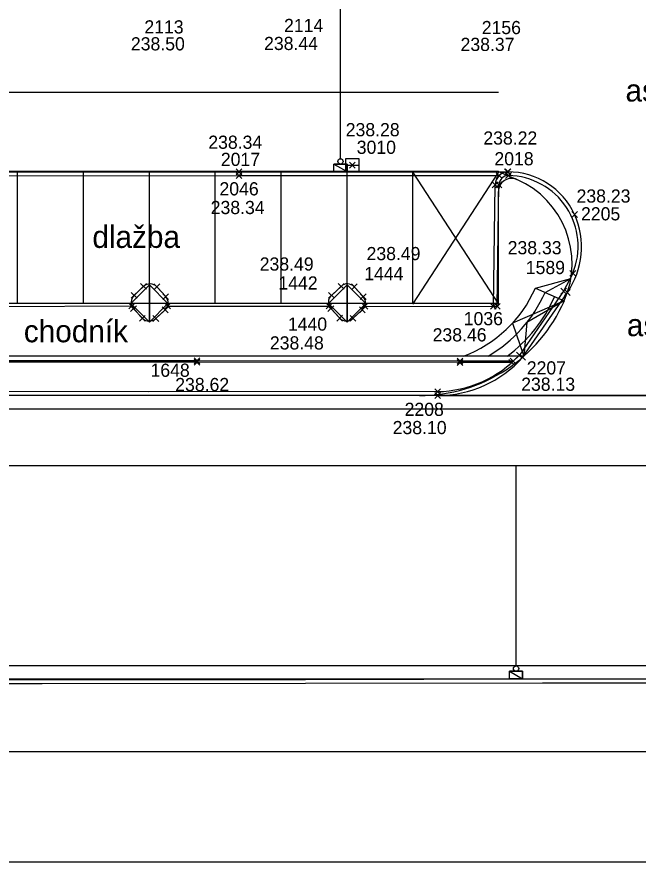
# Model space of a CAD drawing. Extents: x -264165 to -263733, y -1242319 to -1242245.
# Drawn here: x -263947.85 to -263924.28, y -1242319.19 to -1242287.11 of the extents above; entities that cross this region are included whole.
import ezdxf

# ---------------------------------------------------------------- set-up
doc = ezdxf.new("R2010")
doc.units = 0
for name, color, linetype in [('KFA_BOD_CISLO', 7, 'Continuous'), ('KFA_BOD_SYMBOL', 7, 'Continuous'), ('KFA_BOD_VYSKA', 7, 'Continuous'), ('KFA_SO_20-2_OBRUBNIKY_DOLNA_HRANA', 7, 'Continuous'), ('KFA_SO_20-2_OBRUBNIKY_HORNA_HRANA', 7, 'Continuous'), ('KFA_UV_BOD_CISLO', 7, 'Continuous'), ('KFA_UV_BOD_SYMBOL', 7, 'Continuous'), ('KFA_UV_BOD_VYSKA', 7, 'Continuous'), ('POPIS', 7, 'Continuous'), ('PROJEKT_OBRUBNIKY_KOMUNIKACIE', 7, 'Continuous'), ('PROJEKT_TDZ_VODOROVNE', 7, 'Continuous'), ('RAM_NA_TLAC_1-250', 7, 'Continuous'), ('ROZHRANIE_SO_20-1_a_20-2', 7, 'Continuous'), ('SITUACIA_DSP_2D', 7, 'Continuous'), ('SO_20-1_OBRUBNIKY_DOLNA_HRANA', 7, 'Continuous'), ('SO_20-1_OBRUBNIKY_HORNA_HRANA', 7, 'Continuous'), ('ULICNA_VPUST_POKLOP', 7, 'Continuous')]:
    doc.layers.add(name, color=color, linetype=linetype)

msp = doc.modelspace()

# ---------------------------------------------------------------- linework, layer by layer
at = {"layer": 'KFA_BOD_SYMBOL'}
for p, q in [((-263939.535, -1242293.244), (-263939.313, -1242293.022)), ((-263939.313, -1242293.244), (-263939.535, -1242293.022)), ((-263939.534, -1242293.1), (-263939.312, -1242292.88)), ((-263939.312, -1242293.1), (-263939.534, -1242292.88)), ((-263929.666, -1242293.244), (-263929.444, -1242293.022)), ((-263929.444, -1242293.244), (-263929.666, -1242293.022)), ((-263929.348, -1242293.1), (-263929.127, -1242292.879)), ((-263929.127, -1242293.1), (-263929.348, -1242292.879)), ((-263929.33, -1242293.099), (-263929.109, -1242292.877)), ((-263929.109, -1242293.099), (-263929.33, -1242292.877)), ((-263929.311, -1242293.24), (-263929.09, -1242293.019)), ((-263929.09, -1242293.24), (-263929.311, -1242293.019)), ((-263929.818, -1242293.593), (-263929.596, -1242293.372)), ((-263929.596, -1242293.593), (-263929.818, -1242293.372)), ((-263929.676, -1242293.592), (-263929.454, -1242293.37)), ((-263929.454, -1242293.592), (-263929.676, -1242293.37)), ((-263926.801, -1242294.718), (-263926.579, -1242294.497)), ((-263926.579, -1242294.718), (-263926.801, -1242294.497)), ((-263926.871, -1242296.953), (-263926.649, -1242296.731)), ((-263926.649, -1242296.953), (-263926.871, -1242296.731)), ((-263943.155, -1242297.448), (-263942.934, -1242297.227)), ((-263942.934, -1242297.448), (-263943.155, -1242297.227)), ((-263935.66, -1242297.448), (-263935.439, -1242297.227)), ((-263935.439, -1242297.448), (-263935.66, -1242297.227)), ((-263942.652, -1242297.463), (-263942.431, -1242297.242)), ((-263942.431, -1242297.463), (-263942.652, -1242297.242)), ((-263935.16, -1242297.464), (-263934.939, -1242297.242)), ((-263934.939, -1242297.464), (-263935.16, -1242297.242)), ((-263927.218, -1242297.626), (-263926.997, -1242297.404)), ((-263926.997, -1242297.626), (-263927.218, -1242297.404)), ((-263927.078, -1242297.681), (-263926.856, -1242297.46)), ((-263926.856, -1242297.681), (-263927.078, -1242297.46)), ((-263943.513, -1242297.785), (-263943.291, -1242297.565)), ((-263943.291, -1242297.785), (-263943.513, -1242297.565)), ((-263942.316, -1242297.836), (-263942.095, -1242297.616)), ((-263942.095, -1242297.836), (-263942.316, -1242297.616)), ((-263936.025, -1242297.789), (-263935.804, -1242297.568)), ((-263935.804, -1242297.789), (-263936.025, -1242297.568)), ((-263934.824, -1242297.835), (-263934.603, -1242297.613)), ((-263934.603, -1242297.835), (-263934.824, -1242297.613)), ((-263943.6, -1242298.19), (-263943.378, -1242297.968)), ((-263943.378, -1242298.19), (-263943.6, -1242297.968)), ((-263943.534, -1242298.293), (-263943.312, -1242298.073)), ((-263943.312, -1242298.293), (-263943.534, -1242298.073)), ((-263942.334, -1242298.336), (-263942.112, -1242298.116)), ((-263942.112, -1242298.336), (-263942.334, -1242298.116)), ((-263942.242, -1242298.194), (-263942.02, -1242297.974)), ((-263942.02, -1242298.194), (-263942.242, -1242297.974)), ((-263936.115, -1242298.194), (-263935.894, -1242297.972)), ((-263935.894, -1242298.194), (-263936.115, -1242297.972)), ((-263936.052, -1242298.289), (-263935.831, -1242298.069)), ((-263935.831, -1242298.289), (-263936.052, -1242298.069)), ((-263934.856, -1242298.335), (-263934.635, -1242298.113)), ((-263934.635, -1242298.335), (-263934.856, -1242298.113)), ((-263934.759, -1242298.198), (-263934.538, -1242297.978)), ((-263934.538, -1242298.198), (-263934.759, -1242297.978)), ((-263929.883, -1242298.204), (-263929.661, -1242297.984)), ((-263929.661, -1242298.204), (-263929.883, -1242297.984)), ((-263929.736, -1242298.204), (-263929.514, -1242297.984)), ((-263929.514, -1242298.204), (-263929.736, -1242297.984)), ((-263943.198, -1242298.659), (-263942.977, -1242298.438)), ((-263942.977, -1242298.659), (-263943.198, -1242298.438)), ((-263942.692, -1242298.667), (-263942.47, -1242298.447)), ((-263942.47, -1242298.667), (-263942.692, -1242298.447)), ((-263935.715, -1242298.654), (-263935.493, -1242298.434)), ((-263935.493, -1242298.654), (-263935.715, -1242298.434)), ((-263935.209, -1242298.66), (-263934.988, -1242298.44)), ((-263934.988, -1242298.66), (-263935.209, -1242298.44)), ((-263941.127, -1242300.275), (-263940.905, -1242300.053)), ((-263940.905, -1242300.275), (-263941.127, -1242300.053)), ((-263941.127, -1242300.325), (-263940.905, -1242300.103)), ((-263940.905, -1242300.325), (-263941.127, -1242300.103)), ((-263931.152, -1242300.286), (-263930.931, -1242300.066)), ((-263930.931, -1242300.286), (-263931.152, -1242300.066)), ((-263931.152, -1242300.336), (-263930.931, -1242300.116)), ((-263930.931, -1242300.336), (-263931.152, -1242300.116)), ((-263929.186, -1242300.336), (-263928.965, -1242300.116)), ((-263928.965, -1242300.336), (-263929.186, -1242300.116)), ((-263929.131, -1242300.286), (-263928.91, -1242300.066)), ((-263928.91, -1242300.286), (-263929.131, -1242300.066)), ((-263928.899, -1242300.056), (-263928.677, -1242299.835)), ((-263928.677, -1242300.056), (-263928.899, -1242299.835)), ((-263928.775, -1242300.141), (-263928.554, -1242299.921)), ((-263928.554, -1242300.141), (-263928.775, -1242299.921)), ((-263931.998, -1242301.441), (-263931.777, -1242301.22)), ((-263931.777, -1242301.441), (-263931.998, -1242301.22)), ((-263931.998, -1242301.585), (-263931.777, -1242301.363)), ((-263931.777, -1242301.585), (-263931.998, -1242301.363))]:
    msp.add_line(p, q, dxfattribs=at)
at = {"layer": 'KFA_SO_20-2_OBRUBNIKY_DOLNA_HRANA'}
for p, q in [((-263929.772, -1242298.094), (-263929.707, -1242293.482)), ((-263928.665, -1242300.031), (-263926.967, -1242297.57))]:
    msp.add_line(p, q, dxfattribs=at)
for points in [[(-263956.202, -1242292.989), (-263949.428, -1242292.989), (-263939.423, -1242292.99), (-263929.237, -1242292.989)], [(-263956.035, -1242293.137), (-263949.422, -1242293.135), (-263939.424, -1242293.133), (-263929.555, -1242293.133)]]:
    msp.add_lwpolyline(points, dxfattribs=at)
for centre, major_axis, ratio, start_param, end_param in [((-263929.199, -1242293.496), (-0.371, 0.348), 0.999127, 5.506232, 7.008145), ((-263929.234, -1242295.796), (-2.224, 1.716), 0.999648, 4.236262, 5.364518), ((-263929.49, -1242295.837), (-0.77, 2.965), 0.998475, 3.857224, 4.871947), ((-263931.809, -1242297.316), (3.786, 1.868), 0.981258, 4.242641, 5.105702)]:
    msp.add_ellipse(centre, major_axis=major_axis, ratio=ratio, start_param=start_param, end_param=end_param, dxfattribs=at)
at = {"layer": 'KFA_SO_20-2_OBRUBNIKY_HORNA_HRANA'}
for p, q in [((-263929.625, -1242298.094), (-263929.565, -1242293.481)), ((-263943.045, -1242297.337), (-263943.402, -1242297.675)), ((-263942.541, -1242297.352), (-263942.205, -1242297.726)), ((-263935.915, -1242297.678), (-263935.55, -1242297.337)), ((-263935.05, -1242297.353), (-263934.714, -1242297.724)), ((-263949.648, -1242298.106), (-263943.489, -1242298.079)), ((-263943.423, -1242298.183), (-263943.088, -1242298.548)), ((-263942.131, -1242298.084), (-263936.004, -1242298.083)), ((-263935.942, -1242298.179), (-263935.604, -1242298.544)), ((-263934.649, -1242298.088), (-263929.625, -1242298.094)), ((-263942.581, -1242298.557), (-263942.223, -1242298.226)), ((-263934.746, -1242298.224), (-263935.099, -1242298.55))]:
    msp.add_line(p, q, dxfattribs=at)
for points in [[(-263926.76, -1242296.842), (-263927.107, -1242297.515), (-263928.788, -1242299.945)], [(-263929.02, -1242300.176), (-263931.041, -1242300.176), (-263941.016, -1242300.164), (-263949.985, -1242300.162), (-263953.978, -1242300.172), (-263957.09, -1242300.208)], [(-263929.075, -1242300.226), (-263931.041, -1242300.226), (-263941.016, -1242300.214), (-263949.985, -1242300.212), (-263953.978, -1242300.222), (-263957.029, -1242300.257)]]:
    msp.add_lwpolyline(points, dxfattribs=at)
for centre, major_axis, ratio, start_param, end_param in [((-263929.186, -1242293.508), (-0.288, 0.248), 0.999216, 5.45827, 6.921344), ((-263929.25, -1242295.82), (-2.219, 1.523), 0.999965, 3.353406, 5.295124), ((-263942.801, -1242297.607), (-0.359, 0.058), 0.999885, 4.078778, 5.608325), ((-263935.308, -1242297.592), (-0.329, 0.126), 0.999832, 4.255536, 5.836478), ((-263943.156, -1242297.94), (0.063, -0.356), 0.998502, 3.715219, 5.274841), ((-263942.468, -1242297.967), (-0.257, 0.247), 0.99987, 3.094603, 4.64955), ((-263935.68, -1242297.942), (0.018, -0.353), 0.999269, 3.819538, 5.396342), ((-263934.973, -1242297.958), (-0.051, 0.346), 0.999275, 3.70136, 5.300848), ((-263942.83, -1242298.287), (0.196, -0.311), 0.999664, 4.941979, 6.465968), ((-263935.349, -1242298.299), (0.352, -0.034), 0.999726, 4.002913, 5.591201), ((-263931.93, -1242297.064), (3.849, 1.93), 0.988768, 4.261906, 5.072532)]:
    msp.add_ellipse(centre, major_axis=major_axis, ratio=ratio, start_param=start_param, end_param=end_param, dxfattribs=at)
at = {"layer": 'KFA_UV_BOD_SYMBOL'}
for p, q in [((-263935.232, -1242292.846), (-263935.011, -1242292.624)), ((-263935.011, -1242292.846), (-263935.232, -1242292.624))]:
    msp.add_line(p, q, dxfattribs=at)
at = {"layer": 'PROJEKT_OBRUBNIKY_KOMUNIKACIE'}
for p, q in [((-263929.58, -1242292.982), (-263956.068, -1242292.982)), ((-263929.58, -1242292.982), (-263928.879, -1242293.279)), ((-263929.58, -1242297.982), (-263929.58, -1242293.737)), ((-263928.181, -1242297.402), (-263926.833, -1242297.035)), ((-263942.824, -1242297.275), (-263943.531, -1242297.982)), ((-263942.117, -1242297.982), (-263942.824, -1242297.275)), ((-263942.824, -1242297.275), (-263942.824, -1242298.689)), ((-263942.824, -1242298.689), (-263942.824, -1242297.275)), ((-263935.324, -1242297.275), (-263936.031, -1242297.982)), ((-263934.617, -1242297.982), (-263935.324, -1242297.275)), ((-263935.324, -1242297.275), (-263935.324, -1242298.689)), ((-263935.324, -1242298.689), (-263935.324, -1242297.275)), ((-263928.181, -1242297.402), (-263927.081, -1242297.882)), ((-263929.58, -1242297.982), (-263956.068, -1242297.982)), ((-263943.531, -1242297.982), (-263942.824, -1242298.689)), ((-263942.824, -1242298.689), (-263942.117, -1242297.982)), ((-263936.031, -1242297.982), (-263935.324, -1242298.689)), ((-263935.324, -1242298.689), (-263934.617, -1242297.982)), ((-263928.612, -1242299.982), (-263957.036, -1242299.982)), ((-263932.58, -1242301.482), (-263953.068, -1242301.482)), ((-263980.94, -1242312.232), (-263924.192, -1242312.232)), ((-264038.443, -1242314.982), (-263836.403, -1242314.982))]:
    msp.add_line(p, q, dxfattribs=at)
msp.add_lwpolyline([(-263927.081, -1242297.882), (-263929.046, -1242298.73), (-263928.612, -1242299.982)], dxfattribs=at)
for centre, radius, start, end in [((-263929.08, -1242293.737), 0.5, 66.2401, 180), ((-263930.289, -1242296.482), 3.5, 336.4218, 66.2401), ((-263932.58, -1242295.482), 4.8, 290.3641, 336.4218), ((-263932.58, -1242295.482), 6, 270, 336.4218)]:
    msp.add_arc(centre, radius, start, end, dxfattribs=at)
at = {"layer": 'PROJEKT_TDZ_VODOROVNE'}
for p, q in [((-263929.58, -1242289.982), (-263956.068, -1242289.982)), ((-263947.824, -1242297.982), (-263947.824, -1242292.982)), ((-263945.324, -1242297.982), (-263945.324, -1242292.982)), ((-263942.824, -1242297.275), (-263942.824, -1242292.982)), ((-263940.324, -1242297.982), (-263940.324, -1242292.982)), ((-263937.824, -1242297.982), (-263937.824, -1242292.982)), ((-263935.324, -1242297.275), (-263935.324, -1242292.982)), ((-263932.824, -1242297.982), (-263932.824, -1242292.982)), ((-263932.824, -1242298.014), (-263929.58, -1242293.014)), ((-263932.824, -1242293.014), (-263929.58, -1242298.014)), ((-263914.08, -1242301.482), (-263932.58, -1242301.482)), ((-263953.068, -1242301.982), (-263932.58, -1242301.982)), ((-263932.58, -1242301.982), (-263913.841, -1242301.982)), ((-263842.661, -1242311.732), (-263980.94, -1242311.732))]:
    msp.add_line(p, q, dxfattribs=at)
at = {"layer": 'RAM_NA_TLAC_1-250'}
msp.add_lwpolyline([(-264165.363, -1242244.935), (-263732.863, -1242244.935), (-263732.863, -1242319.185), (-264165.363, -1242319.185)], close=True, dxfattribs=at)
at = {"layer": 'ROZHRANIE_SO_20-1_a_20-2'}
msp.add_line((-263931.888, -1242301.474), (-263913.884, -1242301.489), dxfattribs=at)
at = {"layer": 'SITUACIA_DSP_2D'}
for p, q in [((-263935.574, -1242292.492), (-263935.574, -1242284.343)), ((-263935.824, -1242292.692), (-263935.324, -1242292.692)), ((-263935.824, -1242292.982), (-263935.824, -1242292.692)), ((-263935.824, -1242292.692), (-263935.324, -1242292.982)), ((-263935.824, -1242292.692), (-263935.324, -1242292.982)), ((-263935.324, -1242292.692), (-263935.824, -1242292.692)), ((-263935.324, -1242292.692), (-263935.324, -1242292.982)), ((-263935.324, -1242292.982), (-263935.324, -1242292.692)), ((-263935.324, -1242292.982), (-263935.824, -1242292.982)), ((-263929.58, -1242297.982), (-263929.58, -1242293.737)), ((-263927.814, -1242297.562), (-263926.833, -1242297.035)), ((-263927.814, -1242297.562), (-263927.081, -1242297.882)), ((-263929.58, -1242297.982), (-263956.068, -1242297.982)), ((-263928.612, -1242299.982), (-263957.036, -1242299.982)), ((-263932.58, -1242301.482), (-263953.068, -1242301.482)), ((-263904.413, -1242304.147), (-263953.413, -1242304.147)), ((-263928.913, -1242311.742), (-263928.913, -1242304.147)), ((-263929.163, -1242311.942), (-263928.663, -1242311.942)), ((-263929.163, -1242312.232), (-263929.163, -1242311.942)), ((-263929.163, -1242311.942), (-263928.663, -1242312.232)), ((-263929.163, -1242311.942), (-263928.663, -1242312.232)), ((-263928.663, -1242311.942), (-263929.163, -1242311.942)), ((-263928.663, -1242311.942), (-263928.663, -1242312.232)), ((-263928.663, -1242312.232), (-263928.663, -1242311.942)), ((-263980.94, -1242312.232), (-263857.327, -1242312.232)), ((-263928.663, -1242312.232), (-263929.163, -1242312.232)), ((-264038.443, -1242314.982), (-263836.403, -1242314.982))]:
    msp.add_line(p, q, dxfattribs=at)
for points in [[(-263942.117, -1242297.982), (-263942.824, -1242297.275), (-263943.531, -1242297.982), (-263942.824, -1242298.689)], [(-263934.617, -1242297.982), (-263935.324, -1242297.275), (-263936.031, -1242297.982), (-263935.324, -1242298.689)]]:
    msp.add_lwpolyline(points, close=True, dxfattribs=at)
msp.add_lwpolyline([(-263927.081, -1242297.882), (-263928.506, -1242298.713), (-263928.612, -1242299.982)], dxfattribs=at)
for centre in [(-263935.574, -1242292.592), (-263928.913, -1242311.842)]:
    msp.add_circle(centre, 0.1, dxfattribs=at)
for centre, radius, start, end in [((-263929.08, -1242293.737), 0.5, 66.2401, 180), ((-263930.289, -1242296.482), 3.5, 336.4218, 66.2401), ((-263932.58, -1242295.482), 5.2, 300.0733, 336.4218), ((-263932.58, -1242295.482), 5.6, 306.5275, 336.4218), ((-263932.58, -1242295.482), 6, 270, 336.4218)]:
    msp.add_arc(centre, radius, start, end, dxfattribs=at)
at = {"layer": 'SO_20-1_OBRUBNIKY_DOLNA_HRANA'}
for points in [[(-263931.888, -1242301.474), (-263942.877, -1242301.476), (-263953.862, -1242301.477)], [(-264033.805, -1242309.499), (-264025.829, -1242309.934), (-264015.848, -1242310.539), (-264003.863, -1242311.243), (-263994.874, -1242311.606), (-263986.882, -1242311.907), (-263978.856, -1242312.215), (-263970.892, -1242312.243), (-263962.891, -1242312.248), (-263954.893, -1242312.255), (-263953.892, -1242312.266), (-263946.9, -1242312.261), (-263936.904, -1242312.253), (-263927.909, -1242312.236)], [(-263927.909, -1242312.235), (-263920.91, -1242312.234), (-263913.915, -1242312.225), (-263906.912, -1242312.227), (-263898.896, -1242312.208), (-263891.9, -1242312.209), (-263883.905, -1242312.21), (-263878.731, -1242312.212), (-263870.923, -1242312.226), (-263863.907, -1242312.232), (-263855.93, -1242312.232)]]:
    msp.add_lwpolyline(points, dxfattribs=at)
at = {"layer": 'SO_20-1_OBRUBNIKY_HORNA_HRANA'}
for points in [[(-263931.888, -1242301.33), (-263942.861, -1242301.337), (-263953.862, -1242301.33)], [(-264033.819, -1242309.643), (-264025.833, -1242310.082), (-264015.854, -1242310.687), (-264003.872, -1242311.39), (-263994.881, -1242311.753), (-263986.886, -1242312.056), (-263978.896, -1242312.359), (-263970.883, -1242312.387), (-263962.888, -1242312.396), (-263954.878, -1242312.403), (-263953.896, -1242312.41), (-263946.895, -1242312.406), (-263936.899, -1242312.396), (-263927.906, -1242312.382)], [(-263927.907, -1242312.381), (-263920.909, -1242312.378), (-263913.91, -1242312.365), (-263906.907, -1242312.358), (-263898.91, -1242312.357), (-263891.902, -1242312.354), (-263883.907, -1242312.356), (-263878.731, -1242312.358), (-263870.924, -1242312.368), (-263863.913, -1242312.368), (-263855.926, -1242312.378)]]:
    msp.add_lwpolyline(points, dxfattribs=at)
at = {"layer": 'ULICNA_VPUST_POKLOP'}
msp.add_line((-263935.122, -1242292.735), (-263935.122, -1242292.735), dxfattribs=at)
msp.add_lwpolyline([(-263935.372, -1242292.735), (-263935.372, -1242292.485), (-263934.872, -1242292.485), (-263934.872, -1242292.985), (-263935.372, -1242292.985), (-263935.372, -1242292.735), (-263934.872, -1242292.735)], dxfattribs=at)

# ---------------------------------------------------------------- texts
at = {"layer": 'KFA_BOD_CISLO'}
for s, p in [('2113', (-263943.012, -1242287.738)), ('2114', (-263937.715, -1242287.684)), ('2156', (-263930.214, -1242287.763)), ('2017', (-263940.111, -1242292.765)), ('2018', (-263929.733, -1242292.742)), ('2046', (-263940.164, -1242293.883)), ('2205', (-263926.447, -1242294.831)), ('1589', (-263928.543, -1242296.87)), ('1444', (-263934.671, -1242297.101)), ('1442', (-263937.927, -1242297.456)), ('1440', (-263937.568, -1242299.017)), ('1036', (-263930.897, -1242298.81)), ('1648', (-263942.78, -1242300.768)), ('2207', (-263928.505, -1242300.679)), ('2208', (-263933.14, -1242302.252))]:
    msp.add_text(s, height=0.5, dxfattribs=at).set_placement(p)
at = {"layer": 'KFA_BOD_VYSKA'}
for s, p in [('238.50', (-263943.524, -1242288.38)), ('238.44', (-263938.471, -1242288.366)), ('238.37', (-263931.018, -1242288.402)), ('238.22', (-263930.153, -1242291.954)), ('238.34', (-263940.588, -1242292.115)), ('238.23', (-263926.617, -1242294.157)), ('238.34', (-263940.496, -1242294.592)), ('238.33', (-263929.23, -1242296.118)), ('238.49', (-263934.584, -1242296.341)), ('238.49', (-263938.637, -1242296.737)), ('238.46', (-263932.077, -1242299.425)), ('238.48', (-263938.251, -1242299.731)), ('238.62', (-263941.842, -1242301.311)), ('238.13', (-263928.717, -1242301.299)), ('238.10', (-263933.593, -1242302.944))]:
    msp.add_text(s, height=0.5, dxfattribs=at).set_placement(p)
at = {"layer": 'KFA_UV_BOD_CISLO'}
msp.add_text('3010', height=0.5, dxfattribs=at).set_placement((-263934.956, -1242292.306))
at = {"layer": 'KFA_UV_BOD_VYSKA'}
msp.add_text('238.28', height=0.5, dxfattribs=at).set_placement((-263935.374, -1242291.639))
at = {"layer": 'POPIS'}
for s, p in [('asfalt', (-263924.76, -1242290.32)), ('dlažba', (-263944.986, -1242295.876)), ('asfalt', (-263924.707, -1242299.226)), ('chodník', (-263947.586, -1242299.457))]:
    msp.add_text(s, height=0.8438, dxfattribs=at).set_placement(p)

doc.saveas('drawing.dxf')
